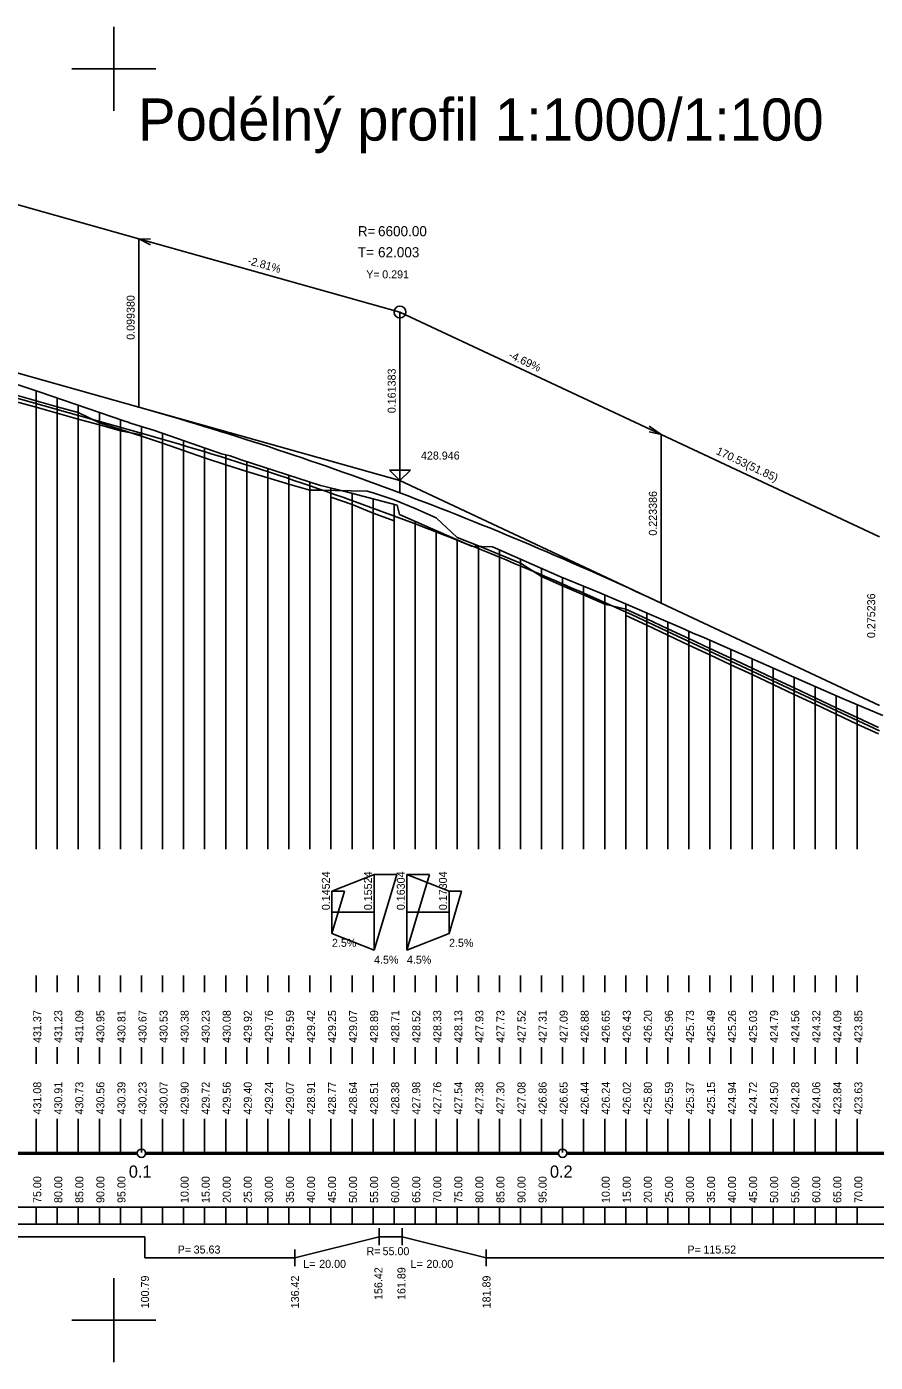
# Model space of a CAD drawing. Extents: x -122 to 738, y -15 to 302.
# Drawn here: x 77.7 to 279.3, y -14.8 to 302.2 of the extents above; entities that cross this region are included whole.
import ezdxf

# ---------------------------------------------------------------- set-up
doc = ezdxf.new("R2010")
doc.units = 0
for name, color, linetype in [('1', 7, 'Continuous'), ('2', 7, 'Continuous'), ('FORMATY', 7, 'Continuous')]:
    doc.layers.add(name, color=color, linetype=linetype)

msp = doc.modelspace()

# ---------------------------------------------------------------- linework, layer by layer
at = {"layer": '1'}
for p, q in [((80.73, 215.52), (67.21, 220.02)), ((80, 215.77), (80, 107)), ((100.8, 208.64), (80.73, 215.52)), ((85, 107), (85, 214.06)), ((90, 212.35), (90, 107)), ((95, 107), (95, 210.63)), ((100, 208.92), (100, 107)), ((102.05, 208.26), (100.8, 208.64)), ((102.2, 208.13), (102.05, 208.26)), ((102.41, 208.09), (102.2, 208.13)), ((102.62, 207.99), (102.41, 208.09)), ((108.1, 206.36), (102.62, 207.99)), ((105, 107), (105, 207.28)), ((124.03, 200.84), (108.1, 206.36)), ((110, 205.7), (110, 107)), ((115, 107), (115, 203.97)), ((120, 202.23), (120, 107)), ((126.04, 200.34), (124.03, 200.84)), ((125, 107), (125, 200.6)), ((128.71, 199.37), (126.04, 200.34)), ((147.55, 193.32), (128.71, 199.37)), ((130, 198.96), (130, 107)), ((135, 107), (135, 197.35)), ((140, 195.75), (140, 107)), ((145, 107), (145, 194.14)), ((148.2, 193.13), (147.55, 193.32)), ((152.71, 192.06), (148.2, 193.13)), ((150, 192.7), (150, 107)), ((165.7, 188.59), (152.71, 192.06)), ((155, 107), (155, 191.45)), ((160, 190.11), (160, 107)), ((165, 107), (165, 188.78)), ((166.26, 186.42), (165.7, 188.59)), ((183.39, 178.87), (166.26, 186.42)), ((170, 184.77), (170, 107)), ((175, 107), (175, 182.57)), ((180, 180.36), (180, 107)), ((188.35, 178.73), (183.39, 178.87)), ((185, 107), (185, 178.82)), ((204.39, 171.73), (188.35, 178.73)), ((190, 178.01), (190, 107)), ((195, 107), (195, 175.82)), ((200, 173.64), (200, 107)), ((213.85, 167.85), (204.39, 171.73)), ((205, 107), (205, 171.47)), ((210, 169.43), (210, 107)), ((233.95, 159.16), (213.85, 167.85)), ((215, 107), (215, 167.35)), ((220, 165.19), (220, 107)), ((225, 107), (225, 163.03)), ((230, 160.86), (230, 107)), ((235.94, 158.27), (233.95, 159.16)), ((235, 107), (235, 158.69)), ((237.96, 157.44), (235.94, 158.27)), ((258.67, 148.36), (237.96, 157.44)), ((240, 156.55), (240, 107)), ((245, 107), (245, 154.35)), ((250, 152.16), (250, 107)), ((255, 107), (255, 149.97)), ((271.44, 142.78), (258.67, 148.36)), ((260, 147.78), (260, 107)), ((265, 107), (265, 145.59)), ((270, 143.41), (270, 107)), ((281.05, 138.69), (271.44, 142.78)), ((275, 107), (275, 141.26)), ((80, 77), (80, 73)), ((85, 73), (85, 77)), ((90, 77), (90, 73)), ((95, 73), (95, 77)), ((100, 77), (100, 73)), ((105, 73), (105, 77)), ((110, 77), (110, 73)), ((115, 73), (115, 77)), ((120, 77), (120, 73)), ((125, 73), (125, 77)), ((130, 77), (130, 73)), ((135, 73), (135, 77)), ((140, 77), (140, 73)), ((145, 73), (145, 77)), ((150, 77), (150, 73)), ((155, 73), (155, 77)), ((160, 77), (160, 73)), ((165, 73), (165, 77)), ((170, 77), (170, 73)), ((175, 73), (175, 77)), ((180, 77), (180, 73)), ((185, 73), (185, 77)), ((190, 77), (190, 73)), ((195, 73), (195, 77)), ((200, 77), (200, 73)), ((205, 73), (205, 77)), ((210, 77), (210, 73)), ((215, 73), (215, 77)), ((220, 77), (220, 73)), ((225, 73), (225, 77)), ((230, 77), (230, 73)), ((235, 73), (235, 77)), ((240, 77), (240, 73)), ((245, 73), (245, 77)), ((250, 77), (250, 73)), ((255, 73), (255, 77)), ((260, 77), (260, 73)), ((265, 73), (265, 77)), ((270, 77), (270, 73)), ((275, 73), (275, 77)), ((80, 60), (80, 56)), ((85, 56), (85, 60)), ((90, 60), (90, 56)), ((95, 56), (95, 60)), ((100, 60), (100, 56)), ((105, 56), (105, 60)), ((110, 60), (110, 56)), ((115, 56), (115, 60)), ((120, 60), (120, 56)), ((125, 56), (125, 60)), ((130, 60), (130, 56)), ((135, 56), (135, 60)), ((140, 60), (140, 56)), ((145, 56), (145, 60)), ((150, 60), (150, 56)), ((155, 56), (155, 60)), ((160, 60), (160, 56)), ((165, 56), (165, 60)), ((170, 60), (170, 56)), ((175, 56), (175, 60)), ((180, 60), (180, 56)), ((185, 56), (185, 60)), ((190, 60), (190, 56)), ((195, 56), (195, 60)), ((200, 60), (200, 56)), ((205, 56), (205, 60)), ((210, 60), (210, 56)), ((215, 56), (215, 60)), ((220, 60), (220, 56)), ((225, 56), (225, 60)), ((230, 60), (230, 56)), ((235, 56), (235, 60)), ((240, 60), (240, 56)), ((245, 56), (245, 60)), ((250, 60), (250, 56)), ((255, 56), (255, 60)), ((260, 60), (260, 56)), ((265, 56), (265, 60)), ((270, 60), (270, 56)), ((275, 56), (275, 60)), ((80, 43), (80, 35)), ((85, 35), (85, 43)), ((90, 43), (90, 35)), ((95, 35), (95, 43)), ((100, 43), (100, 35)), ((105, 35), (105, 43)), ((110, 43), (110, 35)), ((115, 35), (115, 43)), ((120, 43), (120, 35)), ((125, 35), (125, 43)), ((130, 43), (130, 35)), ((135, 35), (135, 43)), ((140, 43), (140, 35)), ((145, 35), (145, 43)), ((150, 43), (150, 35)), ((155, 35), (155, 43)), ((160, 43), (160, 35)), ((165, 35), (165, 43)), ((170, 43), (170, 35)), ((175, 35), (175, 43)), ((180, 43), (180, 35)), ((185, 35), (185, 43)), ((190, 43), (190, 35)), ((195, 35), (195, 43)), ((200, 43), (200, 35)), ((205, 35), (205, 43)), ((210, 43), (210, 35)), ((215, 35), (215, 43)), ((220, 43), (220, 35)), ((225, 35), (225, 43)), ((230, 43), (230, 35)), ((235, 35), (235, 43)), ((240, 43), (240, 35)), ((245, 35), (245, 43)), ((250, 43), (250, 35)), ((255, 35), (255, 43)), ((260, 43), (260, 35)), ((265, 35), (265, 43)), ((270, 43), (270, 35)), ((275, 35), (275, 43)), ((6, 35), (104, 35)), ((106, 35), (204, 35)), ((206, 35), (304, 35)), ((6, 34.6), (104, 34.6)), ((106, 34.6), (204, 34.6)), ((206, 34.6), (304, 34.6)), ((500.51, 22), (5, 22)), ((80, 22), (80, 18)), ((85, 22), (85, 18)), ((90, 22), (90, 18)), ((95, 22), (95, 18)), ((100, 22), (100, 18)), ((105, 22), (105, 18)), ((110, 22), (110, 18)), ((115, 22), (115, 18)), ((120, 22), (120, 18)), ((125, 22), (125, 18)), ((130, 22), (130, 18)), ((135, 22), (135, 18)), ((140, 22), (140, 18)), ((145, 22), (145, 18)), ((150, 22), (150, 18)), ((155, 22), (155, 18)), ((160, 22), (160, 18)), ((165, 22), (165, 18)), ((170, 22), (170, 18)), ((175, 22), (175, 18)), ((180, 22), (180, 18)), ((185, 22), (185, 18)), ((190, 22), (190, 18)), ((195, 22), (195, 18)), ((200, 22), (200, 18)), ((205, 22), (205, 18)), ((210, 22), (210, 18)), ((215, 22), (215, 18)), ((220, 22), (220, 18)), ((225, 22), (225, 18)), ((230, 22), (230, 18)), ((235, 22), (235, 18)), ((240, 22), (240, 18)), ((245, 22), (245, 18)), ((250, 22), (250, 18)), ((255, 22), (255, 18)), ((260, 22), (260, 18)), ((265, 22), (265, 18)), ((270, 22), (270, 18)), ((275, 22), (275, 18)), ((500.51, 18), (5, 18))]:
    msp.add_line(p, q, dxfattribs=at)
for centre in [(105, 34.8), (205, 34.8)]:
    msp.add_circle(centre, 1, dxfattribs=at)
at = {"layer": '2'}
for p, q in [((5, 279.8), (104.38, 251.88)), ((104.38, 251.88), (104.38, 211.88)), ((107.18, 250.39), (104.38, 251.88)), ((104.38, 251.88), (107.18, 251.79)), ((104.38, 251.88), (166.38, 234.46)), ((5, 239.8), (104.38, 211.88)), ((5, 233.8), (104.38, 205.88)), ((166.38, 234.46), (166.38, 191.55)), ((166.38, 234.46), (228.39, 205.39)), ((75, 214.81), (80, 213.4)), ((75, 213.27), (80, 211.87)), ((80, 213.4), (85, 212)), ((80, 211.87), (85, 210.47)), ((85, 212), (90, 210.59)), ((85, 210.47), (90, 209.06)), ((90, 210.59), (95, 208.16)), ((106.32, 211.33), (104.38, 211.88)), ((104.38, 211.88), (166.38, 194.46)), ((108.26, 210.78), (106.32, 211.33)), ((110.19, 210.22), (108.26, 210.78)), ((112.13, 209.66), (110.19, 210.22)), ((114.07, 209.09), (112.13, 209.66)), ((90, 209.06), (95, 207.66)), ((95, 208.16), (100, 206.57)), ((95, 207.66), (100, 206.25)), ((100, 206.57), (105, 205.04)), ((100, 206.25), (105, 205.35)), ((116.01, 208.51), (114.07, 209.09)), ((117.94, 207.93), (116.01, 208.51)), ((119.88, 207.34), (117.94, 207.93)), ((121.82, 206.75), (119.88, 207.34)), ((123.76, 206.15), (121.82, 206.75)), ((125.69, 205.55), (123.76, 206.15)), ((228.39, 205.39), (225.59, 207.4)), ((104.38, 205.88), (106.32, 205.33)), ((105, 205.04), (110, 203.34)), ((106.32, 205.33), (108.26, 204.78)), ((108.26, 204.78), (110.19, 204.22)), ((110, 203.34), (115, 201.62)), ((110.19, 204.22), (112.13, 203.66)), ((112.13, 203.66), (114.07, 203.09)), ((114.07, 203.09), (116.01, 202.51)), ((127.63, 204.94), (125.69, 205.55)), ((129.57, 204.32), (127.63, 204.94)), ((131.51, 203.7), (129.57, 204.32)), ((133.44, 203.07), (131.51, 203.7)), ((135.38, 202.44), (133.44, 203.07)), ((225.59, 206), (228.39, 205.39)), ((228.39, 205.39), (228.39, 165.39)), ((228.39, 205.39), (280.24, 181.08)), ((115, 201.62), (120, 199.9)), ((116.01, 202.51), (117.94, 201.93)), ((117.94, 201.93), (119.88, 201.34)), ((119.88, 201.34), (121.82, 200.75)), ((120, 199.9), (125, 198.17)), ((121.82, 200.75), (123.76, 200.15)), ((123.76, 200.15), (125.69, 199.55)), ((137.32, 201.8), (135.38, 202.44)), ((139.26, 201.16), (137.32, 201.8)), ((141.19, 200.51), (139.26, 201.16)), ((143.13, 199.85), (141.19, 200.51)), ((145.07, 199.19), (143.13, 199.85)), ((125, 198.17), (130, 196.64)), ((125.69, 199.55), (127.63, 198.94)), ((127.63, 198.94), (129.57, 198.32)), ((129.57, 198.32), (131.51, 197.7)), ((130, 196.64), (135, 195.15)), ((131.51, 197.7), (133.44, 197.07)), ((133.44, 197.07), (135.38, 196.44)), ((147.01, 198.53), (145.07, 199.19)), ((148.94, 197.85), (147.01, 198.53)), ((150.88, 197.18), (148.94, 197.85)), ((152.82, 196.49), (150.88, 197.18)), ((166.38, 194.46), (163.88, 196.96)), ((163.88, 196.96), (168.88, 196.96)), ((168.88, 196.96), (166.38, 194.46)), ((135, 195.15), (140, 193.65)), ((135.38, 196.44), (137.32, 195.8)), ((137.32, 195.8), (139.26, 195.16)), ((139.26, 195.16), (141.19, 194.51)), ((140, 193.65), (145, 192.16)), ((141.19, 194.51), (143.13, 193.85)), ((143.13, 193.85), (145.07, 193.19)), ((154.76, 195.8), (152.82, 196.49)), ((156.7, 195.11), (154.76, 195.8)), ((158.63, 194.41), (156.7, 195.11)), ((160.57, 193.7), (158.63, 194.41)), ((162.51, 192.99), (160.57, 193.7)), ((166.38, 194.46), (228.39, 165.39)), ((145, 192.16), (147.21, 192.18)), ((145.07, 193.19), (147.01, 192.53)), ((147.01, 192.53), (148.94, 191.85)), ((147.21, 192.18), (158.6, 191.95)), ((148.94, 191.85), (150.88, 191.18)), ((150, 190.56), (155, 188.82)), ((150.88, 191.18), (152.82, 190.49)), ((152.82, 190.49), (154.76, 189.8)), ((158.6, 191.95), (160, 191.59)), ((160, 191.59), (165, 189.86)), ((164.45, 192.27), (162.51, 192.99)), ((166.38, 191.55), (164.45, 192.27)), ((168.32, 190.82), (166.38, 191.55)), ((170.26, 190.08), (168.32, 190.82)), ((154.76, 189.8), (156.7, 189.11)), ((155, 188.82), (160, 186.75)), ((156.7, 189.11), (158.63, 188.41)), ((158.63, 188.41), (160.57, 187.7)), ((160.57, 187.7), (162.51, 186.99)), ((165, 189.86), (170, 187.82)), ((170, 187.82), (175, 185.63)), ((172.2, 189.34), (170.26, 190.08)), ((174.13, 188.6), (172.2, 189.34)), ((176.07, 187.84), (174.13, 188.6)), ((178.01, 187.09), (176.07, 187.84)), ((179.95, 186.32), (178.01, 187.09)), ((160, 186.75), (165, 184.89)), ((162.51, 186.99), (164.45, 186.27)), ((164.45, 186.27), (166.38, 185.55)), ((166.38, 185.55), (168.32, 184.82)), ((168.32, 184.82), (170.26, 184.08)), ((170.26, 184.08), (172.2, 183.34)), ((175, 185.63), (180, 180.98)), ((181.88, 185.55), (179.95, 186.32)), ((183.82, 184.78), (181.88, 185.55)), ((185.76, 184), (183.82, 184.78)), ((187.7, 183.21), (185.76, 184)), ((172.2, 183.34), (174.13, 182.6)), ((174.13, 182.6), (176.07, 181.84)), ((176.07, 181.84), (178.01, 181.09)), ((178.01, 181.09), (179.95, 180.32)), ((180, 180.98), (185, 178.98)), ((189.63, 182.42), (187.7, 183.21)), ((191.57, 181.62), (189.63, 182.42)), ((193.51, 180.82), (191.57, 181.62)), ((195.45, 180.01), (193.51, 180.82)), ((179.95, 180.32), (181.88, 179.55)), ((181.88, 179.55), (183.82, 178.78)), ((183.82, 178.78), (185.76, 178)), ((185, 178.98), (190, 176.95)), ((185.76, 178), (187.7, 177.21)), ((197.38, 179.2), (195.45, 180.01)), ((199.32, 178.38), (197.38, 179.2)), ((201.26, 177.55), (199.32, 178.38)), ((203.2, 176.72), (201.26, 177.55)), ((187.7, 177.21), (189.63, 176.42)), ((189.63, 176.42), (191.57, 175.62)), ((190, 176.95), (195, 174.87)), ((191.57, 175.62), (193.51, 174.82)), ((193.51, 174.82), (195.45, 174.01)), ((195, 174.87), (200, 171.7)), ((205.13, 175.88), (203.2, 176.72)), ((207.07, 175.04), (205.13, 175.88)), ((209.01, 174.19), (207.07, 175.04)), ((195.45, 174.01), (197.38, 173.2)), ((197.38, 173.2), (199.32, 172.38)), ((199.32, 172.38), (201.26, 171.55)), ((200, 171.7), (205, 169.51)), ((201.26, 171.55), (203.2, 170.72)), ((210.95, 173.34), (209.01, 174.19)), ((212.89, 172.48), (210.95, 173.34)), ((214.82, 171.61), (212.89, 172.48)), ((216.76, 170.74), (214.82, 171.61)), ((203.2, 170.72), (205.13, 169.88)), ((205, 169.51), (210, 167.31)), ((205.13, 169.88), (207.07, 169.04)), ((207.07, 169.04), (209.01, 168.19)), ((209.01, 168.19), (210.95, 167.34)), ((218.7, 169.86), (216.76, 170.74)), ((220.64, 168.98), (218.7, 169.86)), ((222.57, 168.09), (220.64, 168.98)), ((224.51, 167.2), (222.57, 168.09)), ((210, 167.31), (215, 165.13)), ((210.95, 167.34), (212.89, 166.48)), ((212.89, 166.48), (214.82, 165.61)), ((214.82, 165.61), (216.76, 164.74)), ((215, 165.13), (220, 163.94)), ((226.45, 166.3), (224.51, 167.2)), ((228.39, 165.39), (226.45, 166.3)), ((228.39, 165.39), (280.24, 141.08)), ((216.76, 164.74), (218.7, 163.86)), ((218.7, 163.86), (220.64, 162.98)), ((220, 163.94), (225, 161.64)), ((220, 162.41), (225, 160.11)), ((220.64, 162.98), (222.57, 162.09)), ((222.57, 162.09), (224.51, 161.2)), ((224.51, 161.2), (226.45, 160.3)), ((225, 161.64), (230, 159.31)), ((225, 160.11), (230, 157.78)), ((226.45, 160.3), (228.39, 159.39)), ((228.39, 159.39), (280.24, 135.08)), ((230, 159.31), (235, 156.96)), ((230, 157.78), (235, 155.43)), ((235, 156.96), (240, 154.62)), ((235, 155.43), (240, 153.09)), ((240, 154.62), (245, 152.28)), ((240, 153.09), (245, 150.74)), ((245, 152.28), (250, 149.93)), ((245, 150.74), (250, 148.4)), ((250, 149.93), (255, 147.59)), ((250, 148.4), (255, 146.05)), ((255, 147.59), (260, 145.24)), ((255, 146.05), (260, 143.71)), ((260, 145.24), (265, 142.9)), ((260, 143.71), (265, 141.37)), ((265, 142.9), (270, 140.55)), ((265, 141.37), (270, 139.02)), ((270, 140.55), (275, 138.21)), ((270, 139.02), (275, 136.68)), ((275, 138.21), (280, 135.87)), ((275, 136.68), (280, 134.33)), ((150.24, 97), (160.24, 101)), ((160.24, 101), (160.24, 83)), ((160.24, 83), (165.64, 101)), ((165.64, 101), (160.24, 101)), ((168.04, 101), (168.04, 83)), ((168.04, 83), (173.44, 101)), ((173.44, 101), (168.04, 101)), ((168.04, 101), (178.04, 97)), ((150.24, 97), (150.24, 87)), ((150.24, 87), (153.24, 97)), ((153.24, 97), (150.24, 97)), ((178.04, 97), (178.04, 87)), ((178.04, 87), (181.04, 97)), ((181.04, 97), (178.04, 97)), ((150.24, 92), (160.24, 92)), ((168.04, 92), (178.04, 92)), ((160.24, 83), (150.24, 87)), ((178.04, 87), (168.04, 83)), ((161.42, 17), (161.42, 13)), ((166.89, 17), (166.89, 13)), ((33.42, 15), (105.79, 15)), ((105.79, 15), (105.79, 10)), ((141.42, 10), (161.42, 15)), ((161.42, 15), (166.89, 15)), ((166.89, 15), (186.89, 10)), ((105.79, 10), (141.42, 10)), ((141.42, 12), (141.42, 8)), ((186.89, 12), (186.89, 8)), ((186.89, 10), (302.41, 10))]:
    msp.add_line(p, q, dxfattribs=at)
msp.add_circle((166.38, 234.46), 1.4, dxfattribs=at)
at = {"layer": 'FORMATY'}
for p, q in [((98.44, 302.19), (98.44, 282.19)), ((98.44, 302.19), (98.44, 282.19)), ((98.44, 302.19), (98.44, 282.19)), ((98.44, 302.19), (98.44, 282.19)), ((98.44, 302.19), (98.44, 282.19)), ((98.44, 302.19), (98.44, 282.19)), ((98.44, 302.19), (98.44, 282.19)), ((98.44, 302.19), (98.44, 282.19)), ((98.44, 302.19), (98.44, 282.19)), ((88.44, 292.19), (108.44, 292.19)), ((88.44, 292.19), (108.44, 292.19)), ((88.44, 292.19), (108.44, 292.19)), ((88.44, 292.19), (108.44, 292.19)), ((88.44, 292.19), (108.44, 292.19)), ((88.44, 292.19), (108.44, 292.19)), ((88.44, 292.19), (108.44, 292.19)), ((88.44, 292.19), (108.44, 292.19)), ((88.44, 292.19), (108.44, 292.19)), ((98.44, 5.19), (98.44, -14.81)), ((98.44, 5.19), (98.44, -14.81)), ((98.44, 5.19), (98.44, -14.81)), ((88.44, -4.81), (108.44, -4.81)), ((88.44, -4.81), (108.44, -4.81)), ((88.44, -4.81), (108.44, -4.81))]:
    msp.add_line(p, q, dxfattribs=at)

# ---------------------------------------------------------------- texts
at = {"layer": '1'}
for s, p in [('431.08', (81.2, 44)), ('430.91', (86.2, 44)), ('430.73', (91.2, 44)), ('430.56', (96.2, 44)), ('430.39', (101.2, 44)), ('430.23', (106.2, 44)), ('430.07', (111.2, 44)), ('429.90', (116.2, 44)), ('429.72', (121.2, 44)), ('429.56', (126.2, 44)), ('429.40', (131.2, 44)), ('429.24', (136.2, 44)), ('429.07', (141.2, 44)), ('428.91', (146.2, 44)), ('428.77', (151.2, 44)), ('428.64', (156.2, 44)), ('428.51', (161.2, 44)), ('428.38', (166.2, 44)), ('427.98', (171.2, 44)), ('427.76', (176.2, 44)), ('427.54', (181.2, 44)), ('427.38', (186.2, 44)), ('427.30', (191.2, 44)), ('427.08', (196.2, 44)), ('426.86', (201.2, 44)), ('426.65', (206.2, 44)), ('426.44', (211.2, 44)), ('426.24', (216.2, 44)), ('426.02', (221.2, 44)), ('425.80', (226.2, 44)), ('425.59', (231.2, 44)), ('425.37', (236.2, 44)), ('425.15', (241.2, 44)), ('424.94', (246.2, 44)), ('424.72', (251.2, 44)), ('424.50', (256.2, 44)), ('424.28', (261.2, 44)), ('424.06', (266.2, 44)), ('423.84', (271.2, 44)), ('423.63', (276.2, 44)), ('75.00', (81.2, 23)), ('80.00', (86.2, 23)), ('85.00', (91.2, 23)), ('90.00', (96.2, 23)), ('95.00', (101.2, 23)), ('10.00', (116.2, 23)), ('15.00', (121.2, 23)), ('20.00', (126.2, 23)), ('25.00', (131.2, 23)), ('30.00', (136.2, 23)), ('35.00', (141.2, 23)), ('40.00', (146.2, 23)), ('45.00', (151.2, 23)), ('50.00', (156.2, 23)), ('55.00', (161.2, 23)), ('60.00', (166.2, 23)), ('65.00', (171.2, 23)), ('70.00', (176.2, 23)), ('75.00', (181.2, 23)), ('80.00', (186.2, 23)), ('85.00', (191.2, 23)), ('90.00', (196.2, 23)), ('95.00', (201.2, 23)), ('10.00', (216.2, 23)), ('15.00', (221.2, 23)), ('20.00', (226.2, 23)), ('25.00', (231.2, 23)), ('30.00', (236.2, 23)), ('35.00', (241.2, 23)), ('40.00', (246.2, 23)), ('45.00', (251.2, 23)), ('50.00', (256.2, 23)), ('55.00', (261.2, 23)), ('60.00', (266.2, 23)), ('65.00', (271.2, 23)), ('70.00', (276.2, 23))]:
    msp.add_text(s, height=1.9, rotation=90, dxfattribs=at).set_placement(p)
for s, p in [('0.1', (102, 29)), ('0.2', (202, 29))]:
    msp.add_text(s, height=2.9, dxfattribs=at).set_placement(p)
at = {"layer": '2'}
for s, height, p in [('R=', 2.4, (156.38, 252.46)), ('6600.00', 2.4, (161.18, 252.46)), ('T=', 2.4, (156.38, 247.46)), ('62.003', 2.4, (161.18, 247.46)), ('Y=', 1.9, (158.38, 242.46)), ('0.291', 1.9, (162.18, 242.46)), ('428.946', 1.9, (171.38, 199.46)), ('2.5%', 1.9, (150.24, 83.8)), ('2.5%', 1.9, (178.04, 83.8)), ('4.5%', 1.9, (160.24, 79.8)), ('4.5%', 1.9, (168.04, 79.8)), ('P=', 1.9, (113.6, 11)), ('35.63', 1.9, (117.4, 11)), ('P=', 1.9, (234.65, 11)), ('115.52', 1.9, (238.45, 11)), ('20.00', 1.9, (147.22, 7.6)), ('R=', 1.9, (158.46, 10.61)), ('55.00', 1.9, (162.26, 10.61)), ('20.00', 1.9, (172.69, 7.6)), ('L=', 1.9, (143.42, 7.6)), ('L=', 1.9, (168.89, 7.6))]:
    msp.add_text(s, height=height, dxfattribs=at).set_placement(p)
for s, rotation, p in [(' -2.81%', 344.3075, (129.38, 246.06)), ('0.099380', 90, (103.38, 227.88)), (' -4.69%', 334.8812, (191.38, 223.94)), ('0.161383', 90, (165.38, 210.46)), ('170.53(51.85)', 334.8812, (241.31, 200.83)), ('0.223386', 90, (227.39, 181.39)), ('0.275236', 90, (279.24, 157.08)), ('0.14524', 90, (149.74, 92.5)), ('0.15524', 90, (159.74, 92.5)), ('0.16304', 90, (167.54, 92.5)), ('0.17304', 90, (177.54, 92.5)), ('431.37', 90, (81.2, 61)), ('431.23', 90, (86.2, 61)), ('431.09', 90, (91.2, 61)), ('430.95', 90, (96.2, 61)), ('430.81', 90, (101.2, 61)), ('430.67', 90, (106.2, 61)), ('430.53', 90, (111.2, 61)), ('430.38', 90, (116.2, 61)), ('430.23', 90, (121.2, 61)), ('430.08', 90, (126.2, 61)), ('429.92', 90, (131.2, 61)), ('429.76', 90, (136.2, 61)), ('429.59', 90, (141.2, 61)), ('429.42', 90, (146.2, 61)), ('429.25', 90, (151.2, 61)), ('429.07', 90, (156.2, 61)), ('428.89', 90, (161.2, 61)), ('428.71', 90, (166.2, 61)), ('428.52', 90, (171.2, 61)), ('428.33', 90, (176.2, 61)), ('428.13', 90, (181.2, 61)), ('427.93', 90, (186.2, 61)), ('427.73', 90, (191.2, 61)), ('427.52', 90, (196.2, 61)), ('427.31', 90, (201.2, 61)), ('427.09', 90, (206.2, 61)), ('426.88', 90, (211.2, 61)), ('426.65', 90, (216.2, 61)), ('426.43', 90, (221.2, 61)), ('426.20', 90, (226.2, 61)), ('425.96', 90, (231.2, 61)), ('425.73', 90, (236.2, 61)), ('425.49', 90, (241.2, 61)), ('425.26', 90, (246.2, 61)), ('425.03', 90, (251.2, 61)), ('424.79', 90, (256.2, 61)), ('424.56', 90, (261.2, 61)), ('424.32', 90, (266.2, 61)), ('424.09', 90, (271.2, 61)), ('423.85', 90, (276.2, 61)), ('156.42', 90, (162.22, -0.02)), ('161.89', 90, (167.69, -0.02)), ('100.79', 90, (106.79, -2)), ('136.42', 90, (142.42, -2)), ('181.89', 90, (187.89, -2))]:
    msp.add_text(s, height=1.9, rotation=rotation, dxfattribs=at).set_placement(p)
at = {"layer": 'FORMATY'}
msp.add_text('Podélný profil 1:1000/1:100', height=10, dxfattribs=at).set_placement((104.18, 275.16))

doc.saveas('drawing.dxf')
